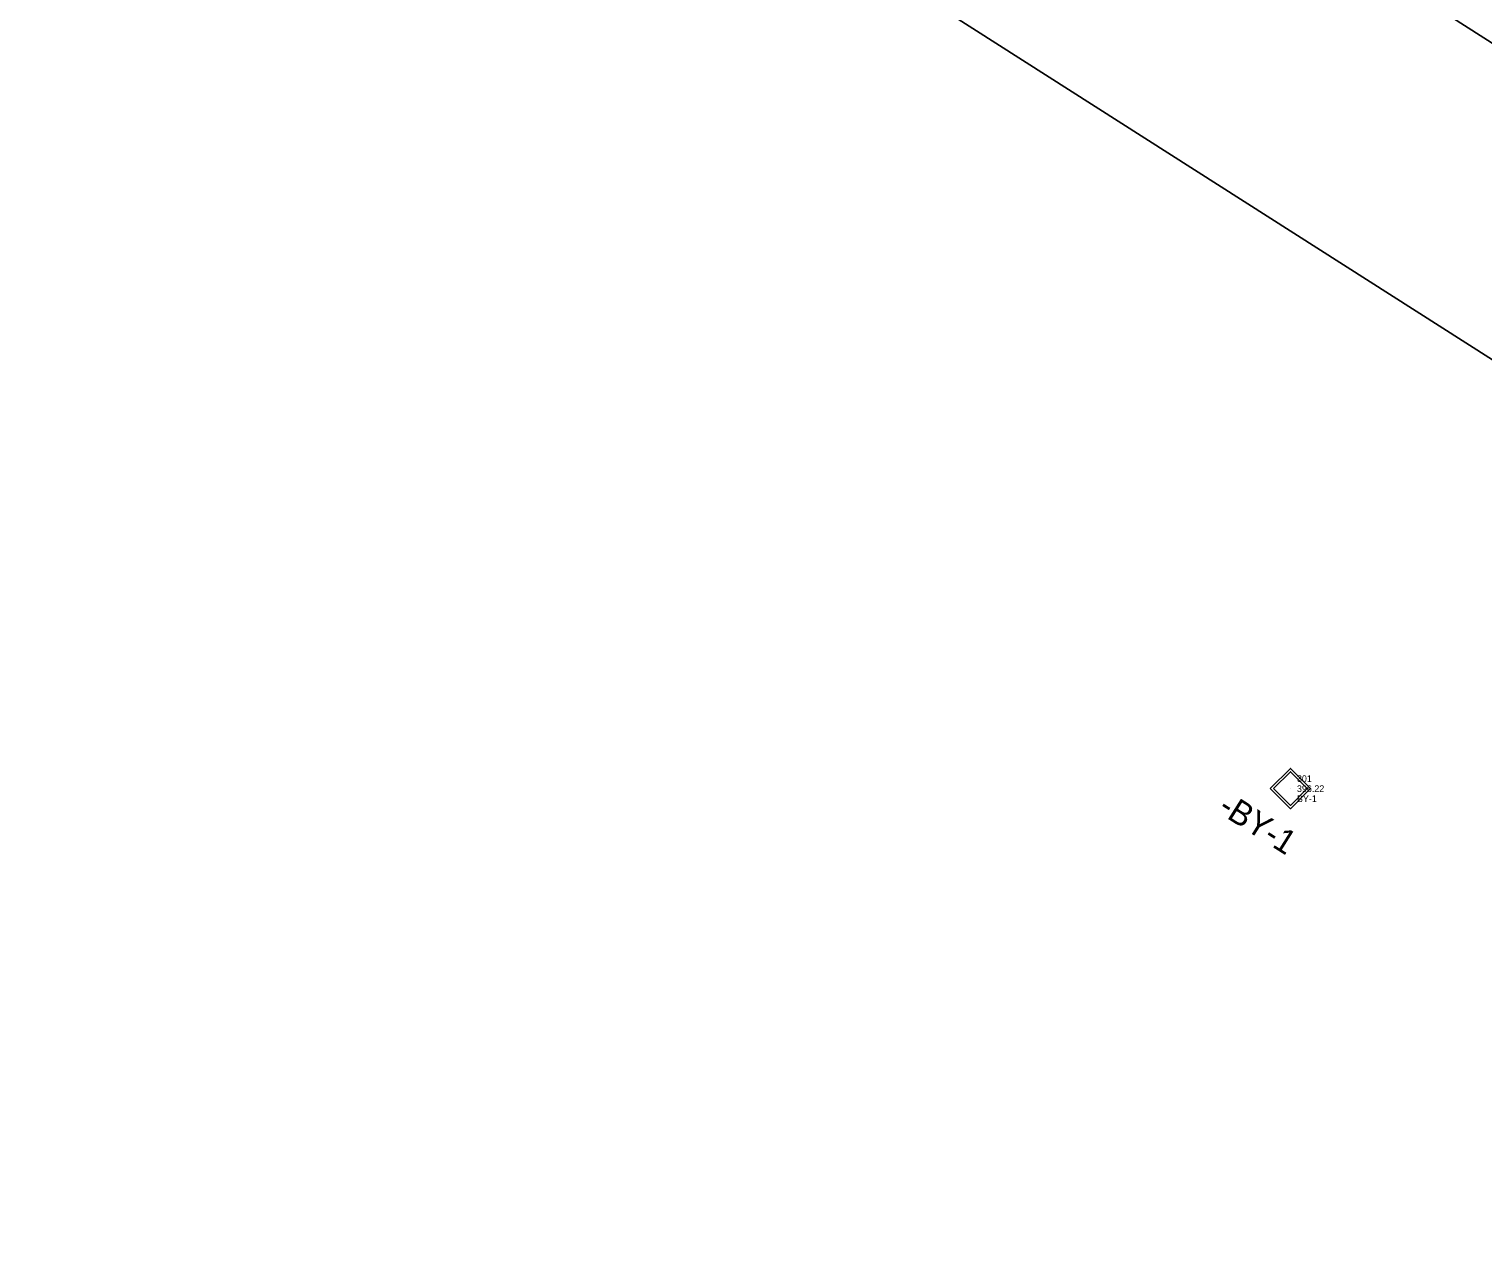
# Model space of a CAD drawing. Extents: x 2022713 to 2279664, y 818739 to 955581.
# Drawn here: x 2024013 to 2024558, y 819968 to 820424 of the extents above; entities that cross this region are included whole.
import ezdxf

# ---------------------------------------------------------------- set-up
doc = ezdxf.new("R2010")
doc.units = 0
for name, color, linetype in [('CTL Supplemental Horizontal and Vertical CELL', 7, 'Continuous'), ('CTL Supplemental Horizontal and Vertical Cogo Comment', 7, 'Continuous'), ('CTL Supplemental Horizontal and Vertical Cogo Elevation', 7, 'Continuous'), ('CTL Supplemental Horizontal and Vertical Cogo Number', 7, 'Continuous'), ('Old_Level_13', 7, 'Continuous'), ('Old_Level_21', 7, 'Continuous'), ('Old_Level_4', 7, 'Continuous')]:
    doc.layers.add(name, color=color, linetype=linetype)

# ---------------------------------------------------------------- blocks, each defined once
blk = doc.blocks.new('CTL SUPPLEMENTAL HORIZONTAL AND VERTICAL')
at = {"layer": 'CTL Supplemental Horizontal and Vertical CELL'}
blk.add_line((0, 0), (0, 0), dxfattribs=at)
blk.add_lwpolyline([(-0.1043, 0.0004), (0.0005, 0.1052), (0.1055, 0.0002), (0.0007, -0.1047)], close=True, dxfattribs=at)

msp = doc.modelspace()

# ---------------------------------------------------------------- linework, layer by layer
at = {"layer": 'Old_Level_13'}
msp.add_line((2024013.44, 820650.02), (2024975.36, 820036.39), dxfattribs=at)
at = {"layer": 'Old_Level_4'}
msp.add_lwpolyline([(2024067.22, 820733.93), (2024116.14, 820703.16), (2024222.96, 820634.96), (2024331.82, 820565.5), (2024444.66, 820493.61), (2024562.31, 820418.39), (2024684.16, 820341.34), (2024850.6, 820234.71), (2025004.49, 820136.43), (2025101.45, 820072.75), (2025176.29, 820021.33), (2025216.3, 819991.16), (2025256.64, 819959.15), (2025296.56, 819925.58), (2025359.9, 819867.87), (2025418.82, 819807.65), (2025459.91, 819763.89)], dxfattribs=at)

# ---------------------------------------------------------------- block references
at = {"layer": 'CTL Supplemental Horizontal and Vertical CELL'}
for xscale, yscale in [(71.99999999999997, 71.99999999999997), (59.999999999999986, 59.999999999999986)]:
    msp.add_blockref('CTL SUPPLEMENTAL HORIZONTAL AND VERTICAL', (2024485.41, 820140.08), dxfattribs=dict(at, xscale=xscale, yscale=yscale))

# ---------------------------------------------------------------- texts
at = {"layer": 'CTL Supplemental Horizontal and Vertical Cogo Comment'}
msp.add_text('BY-1', height=2.5, dxfattribs=at).set_placement((2024487.91, 820135.08))
at = {"layer": 'CTL Supplemental Horizontal and Vertical Cogo Elevation'}
msp.add_text('396.22', height=2.5, dxfattribs=at).set_placement((2024487.91, 820138.83))
at = {"layer": 'CTL Supplemental Horizontal and Vertical Cogo Number'}
msp.add_text('301', height=2.5, dxfattribs=at).set_placement((2024487.91, 820142.58))
at = {"layer": 'Old_Level_21'}
msp.add_text('-BY-1', height=9, rotation=327.7606, dxfattribs=at).set_placement((2024457.92, 820131.37))

doc.saveas('drawing.dxf')
